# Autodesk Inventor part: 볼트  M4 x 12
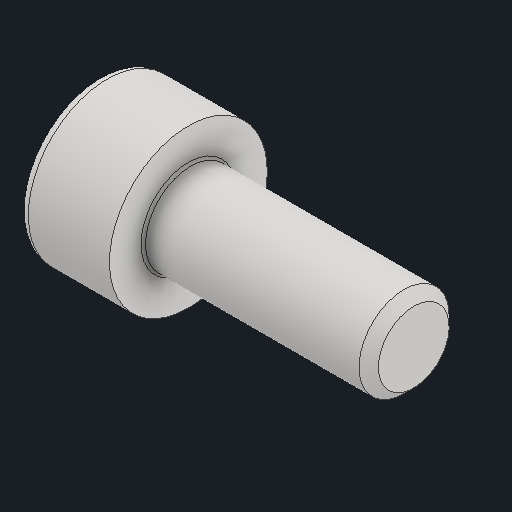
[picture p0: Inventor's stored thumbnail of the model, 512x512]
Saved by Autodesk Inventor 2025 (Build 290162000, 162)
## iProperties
Created: 2025-08
Part Number: 볼트  M4 x 12
Material: 스테인리스강
Description: 6각머리 태핑 나사
Document SubType Name: Modeling
Designer: infra17
Density: 8.08 g/cm^3
Appearance: 기본값
Author: jhkim
Sending System: Autodesk Inventor 2026
Preprocessor: ST-DEVELOPER v20.1
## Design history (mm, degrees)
feature "Solid1"
node "솔리드1"
